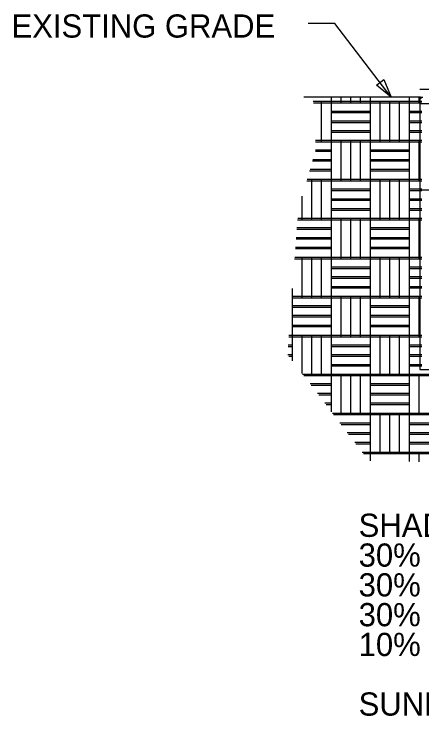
# Model space of a CAD drawing. Extents: x 9966.4 to 10027.9, y 9879.4 to 9942.8.
# Drawn here: x 9966.41 to 9984.77, y 9911.19 to 9942.78 of the extents above; entities that cross this region are included whole.
import ezdxf

# ---------------------------------------------------------------- set-up
doc = ezdxf.new("R2010")
doc.units = 0
for name, color, linetype in [('Default', 7, 'Continuous'), ('G-ANNO-TEXT', 7, 'Continuous'), ('G-ANNO-TTXT', 7, 'Continuous'), ('G-DETL-LINE', 7, 'Continuous'), ('G-DETL-PATT', 7, 'Continuous'), ('L-PLNT-SEED', 7, 'Continuous')]:
    doc.layers.add(name, color=color, linetype=linetype)

# ---------------------------------------------------------------- blocks, each defined once
blk = doc.blocks.new('TERARR')
at = {"layer": 'Default'}
blk.add_lwpolyline([(-0.667, 0.167), (0, 0), (-0.667, -0.167)], close=True, dxfattribs=at)

msp = doc.modelspace()

# ---------------------------------------------------------------- linework, layer by layer
at = {"layer": 'Default'}
for p, q in [((9984.639, 9938.855), (9984.639, 9939.024)), ((9984.639, 9938.785), (9984.639, 9939.024)), ((9984.669, 9939.047), (9984.81, 9939.047)), ((9984.639, 9935.347), (9984.639, 9937.101)), ((9984.639, 9935.277), (9984.639, 9937.031))]:
    msp.add_line(p, q, dxfattribs=at)
at = {"layer": 'G-ANNO-TEXT'}
msp.add_lwpolyline([(9983.389, 9939.047), (9980.852, 9942.362), (9979.641, 9942.362)], dxfattribs=at)
at = {"layer": 'G-ANNO-TTXT'}
msp.add_line((9984.669, 9939.396), (10006.745, 9939.396), dxfattribs=at)
at = {"layer": 'G-DETL-LINE'}
for p, q in [((9984.699, 9939.047), (9979.46, 9939.047)), ((9984.669, 9939.047), (9984.669, 9926.791)), ((9984.669, 9938.75), (10006.741, 9938.75)), ((9984.669, 9934.868), (10006.659, 9934.868)), ((9984.669, 9926.791), (10006.347, 9926.791))]:
    msp.add_line(p, q, dxfattribs=at)
at = {"layer": 'G-DETL-PATT'}
for p, q in [((9980.693, 9938.855), (9980.693, 9939.024)), ((9980.693, 9938.785), (9980.693, 9939.024)), ((9981.131, 9938.855), (9981.131, 9939.024)), ((9981.131, 9938.785), (9981.131, 9939.024)), ((9981.57, 9938.855), (9981.57, 9939.024)), ((9981.57, 9938.785), (9981.57, 9939.024)), ((9982.008, 9938.855), (9982.008, 9939.024)), ((9982.008, 9938.785), (9982.008, 9939.024)), ((9982.447, 9938.855), (9982.447, 9939.024)), ((9982.447, 9938.785), (9982.447, 9939.024)), ((9984.201, 9938.855), (9984.201, 9939.024)), ((9984.201, 9938.785), (9984.201, 9939.024)), ((9979.876, 9938.855), (9984.769, 9938.855)), ((9979.89, 9938.785), (9984.769, 9938.785)), ((9980.254, 9937.101), (9980.254, 9938.855)), ((9980.254, 9937.031), (9980.254, 9938.785)), ((9980.693, 9937.101), (9980.693, 9938.855)), ((9980.693, 9938.855), (9982.447, 9938.855)), ((9980.693, 9937.031), (9980.693, 9938.785)), ((9980.693, 9938.785), (9982.447, 9938.785)), ((9982.447, 9937.101), (9982.447, 9938.855)), ((9982.447, 9937.031), (9982.447, 9938.785)), ((9982.885, 9937.101), (9982.885, 9938.855)), ((9982.885, 9937.031), (9982.885, 9938.785)), ((9983.324, 9937.101), (9983.324, 9938.855)), ((9983.324, 9937.031), (9983.324, 9938.785)), ((9983.762, 9937.101), (9983.762, 9938.855)), ((9983.762, 9937.031), (9983.762, 9938.785)), ((9984.201, 9937.101), (9984.201, 9938.855)), ((9984.201, 9938.855), (9984.769, 9938.855)), ((9984.201, 9937.031), (9984.201, 9938.785)), ((9984.201, 9938.785), (9984.769, 9938.785)), ((9980.693, 9938.417), (9982.447, 9938.417)), ((9980.693, 9938.346), (9982.447, 9938.346)), ((9984.201, 9938.417), (9984.769, 9938.417)), ((9984.201, 9938.346), (9984.769, 9938.346)), ((9980.693, 9937.978), (9982.447, 9937.978)), ((9980.693, 9937.908), (9982.447, 9937.908)), ((9984.201, 9937.978), (9984.769, 9937.978)), ((9984.201, 9937.908), (9984.769, 9937.908)), ((9980.693, 9937.54), (9982.447, 9937.54)), ((9980.693, 9937.469), (9982.447, 9937.469)), ((9984.201, 9937.54), (9984.769, 9937.54)), ((9984.201, 9937.469), (9984.769, 9937.469)), ((9979.983, 9937.101), (9984.769, 9937.101)), ((9980.693, 9935.347), (9980.693, 9937.101)), ((9981.131, 9935.347), (9981.131, 9937.101)), ((9981.57, 9935.347), (9981.57, 9937.101)), ((9982.008, 9935.347), (9982.008, 9937.101)), ((9982.447, 9935.347), (9982.447, 9937.101)), ((9984.201, 9935.347), (9984.201, 9937.101)), ((9979.983, 9937.031), (9984.769, 9937.031)), ((9980.693, 9935.277), (9980.693, 9937.031)), ((9981.131, 9935.277), (9981.131, 9937.031)), ((9981.57, 9935.277), (9981.57, 9937.031)), ((9982.008, 9935.277), (9982.008, 9937.031)), ((9982.447, 9935.277), (9982.447, 9937.031)), ((9984.201, 9935.277), (9984.201, 9937.031)), ((9980.693, 9936.592), (9979.972, 9936.592)), ((9980.693, 9936.663), (9979.983, 9936.663)), ((9984.201, 9936.663), (9982.447, 9936.663)), ((9984.201, 9936.592), (9982.447, 9936.592)), ((9980.693, 9936.154), (9979.842, 9936.154)), ((9980.693, 9936.224), (9979.863, 9936.224)), ((9984.201, 9936.224), (9982.447, 9936.224)), ((9984.201, 9936.154), (9982.447, 9936.154)), ((9980.693, 9935.786), (9979.732, 9935.786)), ((9984.201, 9935.786), (9982.447, 9935.786)), ((9980.693, 9935.715), (9979.712, 9935.715)), ((9984.201, 9935.715), (9982.447, 9935.715)), ((9979.581, 9935.277), (9984.769, 9935.277)), ((9979.602, 9935.347), (9984.769, 9935.347)), ((9979.816, 9933.593), (9979.816, 9935.347)), ((9979.816, 9933.523), (9979.816, 9935.277)), ((9980.254, 9933.593), (9980.254, 9935.347)), ((9980.254, 9933.523), (9980.254, 9935.277)), ((9980.693, 9933.593), (9980.693, 9935.347)), ((9980.693, 9935.347), (9982.447, 9935.347)), ((9980.693, 9933.523), (9980.693, 9935.277)), ((9980.693, 9935.277), (9982.447, 9935.277)), ((9982.447, 9933.593), (9982.447, 9935.347)), ((9982.447, 9933.523), (9982.447, 9935.277)), ((9982.885, 9933.593), (9982.885, 9935.347)), ((9982.885, 9933.523), (9982.885, 9935.277)), ((9983.324, 9933.593), (9983.324, 9935.347)), ((9983.324, 9933.523), (9983.324, 9935.277)), ((9983.762, 9933.593), (9983.762, 9935.347)), ((9983.762, 9933.523), (9983.762, 9935.277)), ((9984.201, 9933.593), (9984.201, 9935.347)), ((9984.201, 9935.347), (9984.769, 9935.347)), ((9984.201, 9933.523), (9984.201, 9935.277)), ((9984.201, 9935.277), (9984.769, 9935.277)), ((9980.693, 9934.909), (9982.447, 9934.909)), ((9980.693, 9934.838), (9982.447, 9934.838)), ((9984.201, 9934.909), (9984.769, 9934.909)), ((9984.201, 9934.838), (9984.769, 9934.838)), ((9979.377, 9933.593), (9979.377, 9934.589)), ((9979.377, 9933.523), (9979.377, 9934.589)), ((9980.693, 9934.47), (9982.447, 9934.47)), ((9980.693, 9934.4), (9982.447, 9934.4)), ((9984.201, 9934.47), (9984.769, 9934.47)), ((9984.201, 9934.4), (9984.769, 9934.4)), ((9980.693, 9934.032), (9982.447, 9934.032)), ((9980.693, 9933.962), (9982.447, 9933.962)), ((9984.201, 9934.032), (9984.769, 9934.032)), ((9984.201, 9933.962), (9984.769, 9933.962)), ((9979.177, 9933.593), (9984.769, 9933.593)), ((9980.693, 9931.84), (9980.693, 9933.593)), ((9981.131, 9931.84), (9981.131, 9933.593)), ((9981.57, 9931.84), (9981.57, 9933.593)), ((9982.008, 9931.84), (9982.008, 9933.593)), ((9982.447, 9931.84), (9982.447, 9933.593)), ((9984.201, 9931.84), (9984.201, 9933.593)), ((9984.639, 9931.84), (9984.639, 9933.593)), ((9979.171, 9933.523), (9984.769, 9933.523)), ((9980.693, 9931.769), (9980.693, 9933.523)), ((9981.131, 9931.769), (9981.131, 9933.523)), ((9981.57, 9931.769), (9981.57, 9933.523)), ((9982.008, 9931.769), (9982.008, 9933.523)), ((9982.447, 9931.769), (9982.447, 9933.523)), ((9984.201, 9931.769), (9984.201, 9933.523)), ((9984.639, 9931.769), (9984.639, 9933.523)), ((9980.693, 9933.085), (9979.138, 9933.085)), ((9980.693, 9933.155), (9979.144, 9933.155)), ((9984.201, 9933.155), (9982.447, 9933.155)), ((9984.201, 9933.085), (9982.447, 9933.085)), ((9980.693, 9932.646), (9979.105, 9932.646)), ((9980.693, 9932.716), (9979.111, 9932.716)), ((9984.201, 9932.716), (9982.447, 9932.716)), ((9984.201, 9932.646), (9982.447, 9932.646)), ((9980.693, 9932.208), (9979.072, 9932.208)), ((9980.693, 9932.278), (9979.078, 9932.278)), ((9984.201, 9932.278), (9982.447, 9932.278)), ((9984.201, 9932.208), (9982.447, 9932.208)), ((9979.039, 9931.769), (9984.769, 9931.769)), ((9979.045, 9931.84), (9984.769, 9931.84)), ((9979.377, 9930.086), (9979.377, 9931.84)), ((9979.377, 9930.015), (9979.377, 9931.769)), ((9979.816, 9930.086), (9979.816, 9931.84)), ((9979.816, 9930.015), (9979.816, 9931.769)), ((9980.254, 9930.086), (9980.254, 9931.84)), ((9980.254, 9930.015), (9980.254, 9931.769)), ((9980.693, 9930.086), (9980.693, 9931.84)), ((9980.693, 9931.84), (9982.447, 9931.84)), ((9980.693, 9930.015), (9980.693, 9931.769)), ((9980.693, 9931.769), (9982.447, 9931.769)), ((9982.447, 9930.086), (9982.447, 9931.84)), ((9982.447, 9930.015), (9982.447, 9931.769)), ((9982.885, 9930.086), (9982.885, 9931.84)), ((9982.885, 9930.015), (9982.885, 9931.769)), ((9983.324, 9930.086), (9983.324, 9931.84)), ((9983.324, 9930.015), (9983.324, 9931.769)), ((9983.762, 9930.086), (9983.762, 9931.84)), ((9983.762, 9930.015), (9983.762, 9931.769)), ((9984.201, 9930.086), (9984.201, 9931.84)), ((9984.201, 9931.84), (9984.769, 9931.84)), ((9984.201, 9930.015), (9984.201, 9931.769)), ((9984.201, 9931.769), (9984.769, 9931.769)), ((9980.693, 9931.401), (9982.447, 9931.401)), ((9984.201, 9931.401), (9984.769, 9931.401)), ((9980.693, 9931.331), (9982.447, 9931.331)), ((9984.201, 9931.331), (9984.769, 9931.331)), ((9980.693, 9930.963), (9982.447, 9930.963)), ((9980.693, 9930.892), (9982.447, 9930.892)), ((9984.201, 9930.963), (9984.769, 9930.963)), ((9984.201, 9930.892), (9984.769, 9930.892)), ((9978.939, 9930.086), (9978.939, 9930.43)), ((9978.939, 9930.015), (9978.939, 9930.43)), ((9980.693, 9930.524), (9982.447, 9930.524)), ((9980.693, 9930.454), (9982.447, 9930.454)), ((9984.201, 9930.524), (9984.769, 9930.524)), ((9984.201, 9930.454), (9984.769, 9930.454)), ((9978.913, 9930.086), (9984.769, 9930.086)), ((9978.939, 9928.332), (9978.939, 9930.086)), ((9980.693, 9928.332), (9980.693, 9930.086)), ((9981.131, 9928.332), (9981.131, 9930.086)), ((9981.57, 9928.332), (9981.57, 9930.086)), ((9982.008, 9928.332), (9982.008, 9930.086)), ((9982.447, 9928.332), (9982.447, 9930.086)), ((9984.201, 9928.332), (9984.201, 9930.086)), ((9984.639, 9928.332), (9984.639, 9930.086)), ((9978.907, 9930.015), (9984.769, 9930.015)), ((9978.939, 9928.261), (9978.939, 9930.015)), ((9980.693, 9928.261), (9980.693, 9930.015)), ((9981.131, 9928.261), (9981.131, 9930.015)), ((9981.57, 9928.261), (9981.57, 9930.015)), ((9982.008, 9928.261), (9982.008, 9930.015)), ((9982.447, 9928.261), (9982.447, 9930.015)), ((9984.201, 9928.261), (9984.201, 9930.015)), ((9984.639, 9928.261), (9984.639, 9930.015)), ((9980.693, 9929.647), (9978.939, 9929.647)), ((9980.693, 9929.577), (9978.939, 9929.577)), ((9984.201, 9929.647), (9982.447, 9929.647)), ((9984.201, 9929.577), (9982.447, 9929.577)), ((9980.693, 9929.209), (9978.939, 9929.209)), ((9980.693, 9929.138), (9978.939, 9929.138)), ((9984.201, 9929.209), (9982.447, 9929.209)), ((9984.201, 9929.138), (9982.447, 9929.138)), ((9980.693, 9928.77), (9978.939, 9928.77)), ((9980.693, 9928.7), (9978.939, 9928.7)), ((9984.201, 9928.77), (9982.447, 9928.77)), ((9984.201, 9928.7), (9982.447, 9928.7)), ((9978.775, 9928.261), (9984.769, 9928.261)), ((9978.775, 9928.261), (9978.939, 9928.261)), ((9978.781, 9928.332), (9984.769, 9928.332)), ((9978.781, 9928.332), (9978.939, 9928.332)), ((9978.939, 9927.181), (9978.939, 9928.332)), ((9978.939, 9927.181), (9978.939, 9928.261)), ((9979.377, 9926.607), (9979.377, 9928.332)), ((9979.377, 9926.607), (9979.377, 9928.261)), ((9979.816, 9926.578), (9979.816, 9928.332)), ((9979.816, 9926.507), (9979.816, 9928.261)), ((9980.254, 9926.578), (9980.254, 9928.332)), ((9980.254, 9926.507), (9980.254, 9928.261)), ((9980.693, 9926.578), (9980.693, 9928.332)), ((9980.693, 9928.332), (9982.447, 9928.332)), ((9980.693, 9926.507), (9980.693, 9928.261)), ((9980.693, 9928.261), (9982.447, 9928.261)), ((9982.447, 9926.578), (9982.447, 9928.332)), ((9982.447, 9926.507), (9982.447, 9928.261)), ((9982.885, 9926.578), (9982.885, 9928.332)), ((9982.885, 9926.507), (9982.885, 9928.261)), ((9983.324, 9926.578), (9983.324, 9928.332)), ((9983.324, 9926.507), (9983.324, 9928.261)), ((9983.762, 9926.578), (9983.762, 9928.332)), ((9983.762, 9926.507), (9983.762, 9928.261)), ((9984.201, 9926.578), (9984.201, 9928.332)), ((9984.201, 9928.332), (9984.769, 9928.332)), ((9984.201, 9926.507), (9984.201, 9928.261)), ((9984.201, 9928.261), (9984.769, 9928.261)), ((9978.748, 9927.893), (9978.939, 9927.893)), ((9980.693, 9927.893), (9982.447, 9927.893)), ((9984.201, 9927.893), (9984.769, 9927.893)), ((9978.743, 9927.823), (9978.939, 9927.823)), ((9980.693, 9927.823), (9982.447, 9927.823)), ((9984.201, 9927.823), (9984.769, 9927.823)), ((9978.73, 9927.455), (9978.939, 9927.455)), ((9978.784, 9927.384), (9978.939, 9927.384)), ((9980.693, 9927.455), (9982.447, 9927.455)), ((9980.693, 9927.384), (9982.447, 9927.384)), ((9984.201, 9927.455), (9984.769, 9927.455)), ((9984.201, 9927.384), (9984.769, 9927.384)), ((9980.693, 9927.016), (9982.447, 9927.016)), ((9980.693, 9926.946), (9982.447, 9926.946)), ((9984.201, 9927.016), (9984.769, 9927.016)), ((9984.201, 9926.946), (9984.769, 9926.946)), ((9979.4, 9926.578), (10006.438, 9926.578)), ((9979.454, 9926.507), (10006.433, 9926.507)), ((9980.693, 9924.886), (9980.693, 9926.578)), ((9980.693, 9924.886), (9980.693, 9926.507)), ((9981.131, 9924.824), (9981.131, 9926.578)), ((9981.131, 9924.753), (9981.131, 9926.507)), ((9981.57, 9924.824), (9981.57, 9926.578)), ((9981.57, 9924.753), (9981.57, 9926.507)), ((9982.008, 9924.824), (9982.008, 9926.578)), ((9982.008, 9924.753), (9982.008, 9926.507)), ((9982.447, 9924.824), (9982.447, 9926.578)), ((9982.447, 9924.753), (9982.447, 9926.507)), ((9984.201, 9924.824), (9984.201, 9926.578)), ((9984.201, 9924.753), (9984.201, 9926.507)), ((9984.639, 9924.824), (9984.639, 9926.578)), ((9984.639, 9924.753), (9984.639, 9926.507)), ((9980.693, 9926.139), (9979.735, 9926.139)), ((9980.693, 9926.069), (9979.789, 9926.069)), ((9984.201, 9926.139), (9982.447, 9926.139)), ((9984.201, 9926.069), (9982.447, 9926.069)), ((9980.693, 9925.701), (9980.07, 9925.701)), ((9984.201, 9925.701), (9982.447, 9925.701)), ((9980.693, 9925.63), (9980.124, 9925.63)), ((9984.201, 9925.63), (9982.447, 9925.63)), ((9980.693, 9925.262), (9980.405, 9925.262)), ((9980.693, 9925.192), (9980.459, 9925.192)), ((9984.201, 9925.262), (9982.447, 9925.262)), ((9984.201, 9925.192), (9982.447, 9925.192)), ((9980.74, 9924.824), (10006.208, 9924.824)), ((9980.74, 9924.824), (9982.447, 9924.824)), ((9980.794, 9924.753), (10006.196, 9924.753)), ((9980.794, 9924.753), (9982.447, 9924.753)), ((9982.447, 9923.07), (9982.447, 9924.824)), ((9982.447, 9922.999), (9982.447, 9924.753)), ((9982.885, 9923.07), (9982.885, 9924.824)), ((9982.885, 9922.999), (9982.885, 9924.753)), ((9983.324, 9923.07), (9983.324, 9924.824)), ((9983.324, 9922.999), (9983.324, 9924.753)), ((9983.762, 9923.07), (9983.762, 9924.824)), ((9983.762, 9922.999), (9983.762, 9924.753)), ((9984.201, 9923.07), (9984.201, 9924.824)), ((9984.201, 9924.824), (9985.954, 9924.824)), ((9984.201, 9922.999), (9984.201, 9924.753)), ((9984.201, 9924.753), (9985.954, 9924.753)), ((9981.075, 9924.385), (9982.447, 9924.385)), ((9981.129, 9924.315), (9982.447, 9924.315)), ((9984.201, 9924.385), (9985.954, 9924.385)), ((9984.201, 9924.315), (9985.954, 9924.315)), ((9981.41, 9923.947), (9982.447, 9923.947)), ((9981.464, 9923.876), (9982.447, 9923.876)), ((9984.201, 9923.947), (9985.954, 9923.947)), ((9984.201, 9923.876), (9985.954, 9923.876)), ((9981.745, 9923.508), (9982.447, 9923.508)), ((9984.201, 9923.508), (9985.954, 9923.508)), ((9981.799, 9923.438), (9982.447, 9923.438)), ((9984.201, 9923.438), (9985.954, 9923.438)), ((9982.08, 9923.07), (10003.425, 9923.07)), ((9982.134, 9922.999), (10002.781, 9922.999)), ((9982.447, 9922.681), (9982.447, 9923.07)), ((9982.447, 9922.681), (9982.447, 9922.999)), ((9984.201, 9922.64), (9984.201, 9923.07)), ((9984.201, 9922.64), (9984.201, 9922.999)), ((9984.639, 9922.629), (9984.639, 9923.07)), ((9984.639, 9922.629), (9984.639, 9922.999))]:
    msp.add_line(p, q, dxfattribs=at)
at = {"layer": 'L-PLNT-SEED'}
for p, q in [((9984.687, 9938.988), (9984.669, 9939.003)), ((9984.687, 9938.987), (9984.685, 9938.988)), ((9984.687, 9939.047), (9984.687, 9938.988)), ((9984.687, 9938.988), (9984.742, 9939.032)), ((9984.687, 9938.987), (9984.689, 9938.988)), ((9984.687, 9938.988), (9984.687, 9938.987))]:
    msp.add_line(p, q, dxfattribs=at)

# ---------------------------------------------------------------- block references
at = {"layer": 'G-ANNO-TEXT', "xscale": 1.24992, "yscale": 1.2499200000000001, "rotation": -52.57489474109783}
msp.add_blockref('TERARR', (9983.389, 9939.047), dxfattribs=at)

# ---------------------------------------------------------------- texts
at = {"layer": 'G-ANNO-TEXT'}
for s, p in [('EXISTING GRADE', (9966.297, 9941.722)), ('SHADY MIX', (9981.92, 9919.252)), ('30% PETITE TALL FESCUE', (9981.92, 9917.911)), ('30% TAOS TALL FESCUE', (9981.92, 9916.57)), ('30% LEXINGTON TALL FESCUE', (9981.92, 9915.229)), ('10% BLUE SAPPHIRE KENTUCKY BLUEGRASS', (9981.92, 9913.889)), ('SUNNY MIX PREMIUM', (9981.92, 9911.207))]:
    msp.add_text(s, height=1.044, dxfattribs=at).set_placement(p)

doc.saveas('drawing.dxf')
